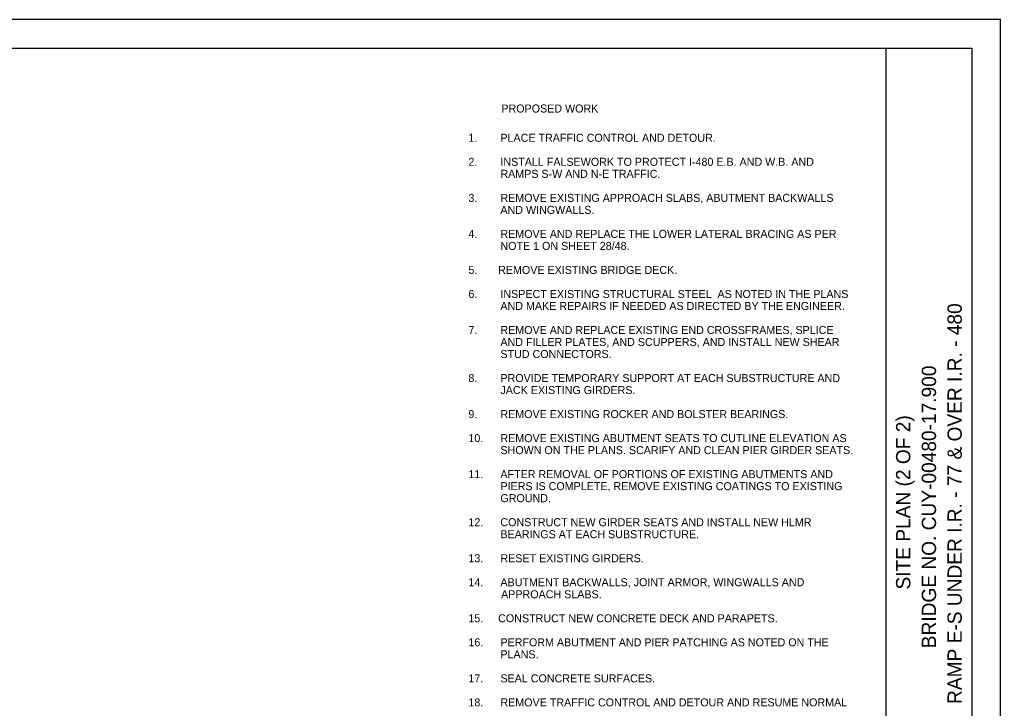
# Model space of a CAD drawing. Extents: x -0.3 to 34, y 0 to 22.
# Drawn here: x 16.85 to 34, y 9.96 to 22 of the extents above; entities that cross this region are included whole.
import ezdxf

# ---------------------------------------------------------------- set-up
doc = ezdxf.new("R2010")
doc.units = 0
for name, color, linetype in [('BR_P_Gen_Text', 7, 'Continuous'), ('SH_Border', 7, 'Continuous'), ('SH_Cut_Line', 7, 'Continuous'), ('SH_Data', 7, 'Continuous'), ('SH_Text', 7, 'Continuous')]:
    doc.layers.add(name, color=color, linetype=linetype)

msp = doc.modelspace()

# ---------------------------------------------------------------- linework, layer by layer
at = {"layer": 'SH_Border'}
msp.add_line((32, 0.5), (32, 21.5), dxfattribs=at)
msp.add_lwpolyline([(1.5, 21.5), (33.5, 21.5), (33.5, 0.5), (1.5, 0.5)], close=True, dxfattribs=at)
at = {"layer": 'SH_Cut_Line'}
msp.add_lwpolyline([(0, 0), (34, 0), (34, 22), (0, 22)], close=True, dxfattribs=at)

# ---------------------------------------------------------------- texts
at = {"layer": 'BR_P_Gen_Text'}
for s, p in [('1.', (24.697, 19.864)), ('PLACE TRAFFIC CONTROL AND DETOUR. ', (25.257, 19.864)), ('2.  ', (24.697, 19.444)), ('INSTALL FALSEWORK TO PROTECT I-480 E.B. AND W.B. AND ', (25.257, 19.444)), ('RAMPS S-W AND N-E TRAFFIC.', (25.257, 19.234)), ('3.', (24.697, 18.814)), ('REMOVE EXISTING APPROACH SLABS, ABUTMENT BACKWALLS ', (25.257, 18.814)), ('AND WINGWALLS.', (25.257, 18.604)), ('4.', (24.697, 18.184)), ('REMOVE AND REPLACE THE LOWER LATERAL BRACING AS PER', (25.257, 18.184)), ('NOTE 1 ON SHEET 28/48.', (25.257, 17.974)), ('5.       REMOVE EXISTING BRIDGE DECK.', (24.697, 17.554)), ('6.', (24.697, 17.134)), ('INSPECT EXISTING STRUCTURAL STEEL  AS NOTED IN THE PLANS', (25.257, 17.134)), ('AND MAKE REPAIRS IF NEEDED AS DIRECTED BY THE ENGINEER.', (25.257, 16.924)), ('7.', (24.697, 16.504)), ('REMOVE AND REPLACE EXISTING END CROSSFRAMES, SPLICE ', (25.257, 16.504)), ('AND FILLER PLATES, AND SCUPPERS, AND INSTALL NEW SHEAR ', (25.257, 16.294)), ('STUD CONNECTORS.', (25.257, 16.084)), ('8.', (24.697, 15.664)), ('PROVIDE TEMPORARY SUPPORT AT EACH SUBSTRUCTURE AND ', (25.257, 15.664)), ('JACK EXISTING GIRDERS.', (25.257, 15.454)), ('9.', (24.697, 15.034)), ('REMOVE EXISTING ROCKER AND BOLSTER BEARINGS.', (25.257, 15.034)), ('10.', (24.697, 14.614)), ('REMOVE EXISTING ABUTMENT SEATS TO CUTLINE ELEVATION AS ', (25.257, 14.614)), ('SHOWN ON THE PLANS. SCARIFY AND CLEAN PIER GIRDER SEATS.', (25.257, 14.404)), ('11.', (24.697, 13.984)), ('AFTER REMOVAL OF PORTIONS OF EXISTING ABUTMENTS AND ', (25.257, 13.984)), ('PIERS IS COMPLETE, REMOVE EXISTING COATINGS TO EXISTING ', (25.257, 13.774)), ('GROUND.', (25.257, 13.564)), ('12.', (24.697, 13.144)), ('CONSTRUCT NEW GIRDER SEATS AND INSTALL NEW HLMR ', (25.257, 13.144)), ('BEARINGS AT EACH SUBSTRUCTURE.', (25.257, 12.934)), ('13.', (24.697, 12.514)), ('RESET EXISTING GIRDERS.', (25.257, 12.514)), ('14.  ', (24.697, 12.094)), ('ABUTMENT BACKWALLS, JOINT ARMOR, WINGWALLS AND ', (25.257, 12.094)), ('           APPROACH SLABS.', (24.697, 11.884)), ('15.     CONSTRUCT NEW CONCRETE DECK AND PARAPETS.', (24.697, 11.464)), ('16.', (24.697, 11.044)), ('PERFORM ABUTMENT AND PIER PATCHING AS NOTED ON THE ', (25.257, 11.044)), ('PLANS.', (25.257, 10.834)), ('17.', (24.697, 10.414)), ('SEAL CONCRETE SURFACES.', (25.257, 10.414)), ('18.', (24.697, 9.994)), ('REMOVE TRAFFIC CONTROL AND DETOUR AND RESUME NORMAL ', (25.257, 9.994))]:
    msp.add_text(s, height=0.14, dxfattribs=at).set_placement(p)
at = {"layer": 'SH_Data'}
for s, p in [('RAMP E-S UNDER I.R. - 77 & OVER I.R. - 480', (33.325, 10.037)), ('BRIDGE NO. CUY-00480-17.900', (32.875, 11.01)), ('SITE PLAN (2 OF 2)', (32.425, 12.037))]:
    msp.add_text(s, height=0.25, rotation=90, dxfattribs=at).set_placement(p)
at = {"layer": 'SH_Text'}
msp.add_text('PROPOSED WORK', height=0.14, dxfattribs=at).set_placement((25.274, 20.376))

doc.saveas('drawing.dxf')
